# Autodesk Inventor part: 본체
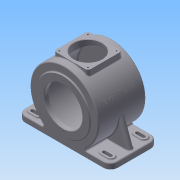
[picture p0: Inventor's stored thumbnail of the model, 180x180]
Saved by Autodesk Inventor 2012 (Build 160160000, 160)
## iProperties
Created: 2015-06
Part Number: 본체
Material: 알루미늄-6061
Document SubType Name: Modeling
Designer: User
Density: 2.71 g/cm^3
Mass: 3275.37 g
Surface Area: 2299.65 cm^2
Volume: 1208.62 cm^3
Author: User
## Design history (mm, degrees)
sketch "스케치1"
  geometry: C1 r 85 at (0, 0); 1 further point
  constraints: 1 centre point, 1 coincident
  dimensions: "d0" = 170 diameter of C1
extrude "돌출1" new body sketch "스케치1" stored distance "d1" = 118; taper "d2" = 0 deg
node "작업 평면1"
sketch "스케치2"
  geometry: L1 (-97, 59)-(97, 59); L2 (115, 41)-(115, -41); L3 (97, -59)-(-97, -59); L4 (-115, -41)-(-115, 41); A1 r 18 centre (-97, 41) between (-97, 59) and (-115, 41); A2 r 18 centre (-97, -41) between (-115, -41) and (-97, -59); A3 r 18 centre (97, -41) between (97, -59) and (115, -41); A4 r 18 centre (97, 41) between (115, 41) and (97, 59); 6 further points
  constraints: 8 end point, 8 point on circle, 8 tangent, 6 point on line, 4 centre point, 3 equal radius, 2 midpoint, 2 parallel, 1 horizontal, 1 horizontal alignment, 1 perpendicular, 1 vertical alignment
  dimensions: "d4" = 118 distance of point (-115, -59) point (-115, 59); "d5" = 230 distance of point (-115, 59) point (115, 59); "d6" = 18 radius of A1
extrude "돌출2" join sketch "스케치2" distance "d7" = 14; taper "d8" = 0 deg
sketch "스케치3"
  geometry: L1 (-42.5, 42.5)-(42.5, 42.5); L2 (42.5, 42.5)-(42.5, -42.5); L3 (42.5, -42.5)-(-42.5, -42.5); L4 (-42.5, -42.5)-(-42.5, 42.5); 3 further points
  constraints: 8 end point, 2 midpoint, 2 parallel, 2 perpendicular, 1 horizontal, 1 horizontal alignment, 1 vertical alignment
  dimensions: "d9" = 85 distance of L1.start L1.end
extrude "돌출3" join sketch "스케치3" distance "d10" = 88; taper "d11" = 0 deg
sketch "스케치4"
  geometry: C1 r 65 at (0, 0); A1 r 85 centre (0, 0) between (46.733, -71) and (-46.733, -71) reference
  constraints: 1 centre point, 1 coincident
  dimensions: "d12" = 130 diameter of C1
extrude "돌출4" join sketch "스케치4" distance "d13" = 3; taper "d14" = 0 deg
sketch "스케치5"
  geometry: C1 r 65 at (0, 0); A1 r 85 centre (0, 0) between (46.733, -71) and (-46.733, -71) reference
  constraints: 1 centre point, 1 coincident
  dimensions: "d15" = 130 diameter of C1
extrude "돌출5" join sketch "스케치5" distance "d16" = 13; taper "d17" = 0 deg
sketch "스케치6"
  geometry: L1 (-46.733, -59)-(-97, -59) reference; L2 (-97, 50)-(-81, 50); L3 (-81, 32)-(-97, 32); L4 (-97, -32)-(-81, -32); L5 (-81, -50)-(-97, -50); L6 (81, 50)-(97, 50); L7 (97, 32)-(81, 32); L8 (81, -32)-(97, -32); L9 (97, -50)-(81, -50); L10 (115, -41)-(115, 41) reference; L11 (-81, 45)-(-97, 45); L12 (-97, 37)-(-81, 37); L13 (97, 45)-(81, 45); L14 (81, 37)-(97, 37); L15 (97, -37)-(81, -37); L16 (81, -45)-(97, -45); L17 (-81, -37)-(-97, -37); L18 (-97, -45)-(-81, -45); A1 r 18 centre (-97, 41) between (-97, 59) and (-115, 41) reference; A2 r 18 centre (-97, -41) between (-115, -41) and (-97, -59) reference; A3 r 9 centre (-81, 41) between (-81, 32) and (-81, 50); A4 r 9 centre (-97, 41) between (-97, 50) and (-97, 32); A5 r 9 centre (-81, -41) between (-81, -50) and (-81, -32); A6 r 9 centre (-97, -41) between (-97, -32) and (-97, -50); A7 r 9 centre (97, 41) between (97, 32) and (97, 50); A8 r 9 centre (81, 41) between (81, 50) and (81, 32); A9 r 9 centre (97, -41) between (97, -50) and (97, -32); A10 r 9 centre (81, -41) between (81, -32) and (81, -50); A11 r 4 centre (-97, 41) between (-97, 45) and (-97, 37); A12 r 4 centre (-81, 41) between (-81, 37) and (-81, 45); A13 r 4 centre (81, 41) between (81, 45) and (81, 37); A14 r 4 centre (97, 41) between (97, 37) and (97, 45); A15 r 4 centre (81, -41) between (81, -37) and (81, -45); A16 r 4 centre (97, -41) between (97, -45) and (97, -37); A17 r 4 centre (-97, -41) between (-97, -37) and (-97, -45); A18 r 4 centre (-81, -41) between (-81, -45) and (-81, -37); 1 further point
  constraints: 32 end point, 32 point on circle, 16 centre point, 16 tangent, 12 parallel, 6 equal radius, 4 coincident, 2 equal length, 2 horizontal alignment, 2 vertical alignment, 12 other
  dimensions: "d18" = 16 distance of A3.centre A1.centre; "d19" = 18 distance between parallel lines of L3 L2; "d20" = 18 distance from line of A7.centre L10; "d21" = 8 distance between parallel lines of L12 L11
extrude "돌출6" join sketch "스케치6" distance "d22" = 3; taper "d23" = 0 deg
extrude "돌출7" cut sketch "스케치6" stored distance "d24" = 30; taper "d25" = 0 deg
sketch "스케치7"
  geometry: L1 (-115, -71)-(-97, -71) reference; L2 (-109, -71)-(-84.87, -4.703); L3 (97, -71)-(115, -71) reference; L4 (109, -71)-(84.87, -4.703); L5 (-84.87, -4.703)-(84.87, -4.703); L6 (-109, -71)-(109, -71); A1 r 85 centre (0, 0) between (46.733, -71) and (-46.733, -71) reference; 1 further point
  constraints: 8 end point, 2 point on circle, 2 point on line
  dimensions: "d26" = 6 distance of L2.start L1.start; "d27" = 110 deg angle of L2 L1; "d28" = 6 distance of L3.end L4.start; "d29" = 110 deg angle of L3 L4
extrude "돌출8" join sketch "스케치7" stored distance "d30" = 15; taper "d31" = 0 deg
node "작업 평면2"
  node "작업축2"
sketch "스케치11"
  geometry: L1 (40.533, -6.549)-(-40.533, -6.549); L2 (-40.533, -6.549)-(-40.533, 6.549); L3 (-40.533, 6.549)-(40.533, 6.549); L4 (40.533, 6.549)-(40.533, -6.549); 4 further points
  constraints: 2 horizontal alignment, 2 midpoint, 1 coincident, 1 vertical alignment, 2 other
feature "엠보싱1" sketch "스케치11" dims "d0" = 170, "d61" = 0.5, "d62" = 0
sketch "스케치8"
  geometry: L1 (-85, 82.6)-(-85, -82.6) reference; L2 (88, 42.5)-(88, -42.5) reference; L3 (-65, 59)-(65, 59) reference; L4 (65, -59)-(-65, -59) reference; L5 (0, 51)-(77, 51); L6 (77, 51)-(77, -51); L7 (77, -51)-(0, -51); L8 (0, 51)-(0, -51); 1 further point
  constraints: 10 end point, 3 parallel, 1 vertical, 1 vertical alignment
  dimensions: "d32" = 8 distance between parallel lines of L4 L7; "d33" = 8 distance between parallel lines of L5 L3; "d34" = 11 distance between parallel lines of L2 L6
revolve "회전1" sketch "스케치8" stored, may be unused: angle "d35" = 90 deg
hole "구멍1" diameter "d38" = 95; stored, may be unused: countersink angle "d42" = 90 deg, drill point angle "d44" = 118 deg; dims "d36" = 10, "d37" = 10, "d39" = 6, "d40" = 4, "d41" = 2, "d43" = 50
sketch "스케치9"
  geometry: C1 r 35 at (0, 0); 1 further point
  constraints: 1 centre point, 1 coincident
  dimensions: "d45" = 70 diameter of C1
extrude "돌출9" cut sketch "스케치9" distance "d46" = 30; taper "d47" = 0 deg
sketch "스케치10"
  geometry: C1 r 77 at (0, 0) reference; C2 r 31 at (0, 0)
  constraints: 1 centre point, 1 coincident
  dimensions: "d48" = 62 diameter of C2
extrude "돌출10" join sketch "스케치10" distance "d49" = 3.5; taper "d50" = -25 deg
hole "구멍2" diameter "d53" = 30; stored, may be unused: countersink angle "d57" = 90 deg, drill point angle "d59" = 0 deg; dims "d51" = 10, "d52" = 10, "d54" = 6, "d55" = 47, "d56" = 14, "d58" = 17
sketch "스케치12"
  geometry: L1 (-35.5, 35.5)-(35.5, 35.5); L2 (35.5, 35.5)-(35.5, -35.5); L3 (35.5, -35.5)-(-35.5, -35.5); L4 (-35.5, -35.5)-(-35.5, 35.5); C1 r 35 at (0, 0) reference; 6 further points
  constraints: 8 end point, 4 coincident, 2 midpoint, 2 parallel, 2 perpendicular, 1 horizontal, 1 horizontal alignment, 1 vertical alignment
  dimensions: "d63" = 71 distance of L1.start L1.end
hole "구멍3" sketch "스케치12" at (-35.5, 35.5), (35.5, 35.5), (35.5, -35.5), (-35.5, -35.5) diameter "d64" = 3.242; stored, may be unused: countersink angle "d68" = 90 deg, drill point angle "d70" = 0 deg; dims "d65" = 10, "d66" = 47, "d67" = 14, "d69" = 13
chamfer "모따기1" distance "d71" = 1; stored, may be unused: second distance "d72" = 2, angle "d73" = 45 deg
chamfer "모따기2" distance "d74" = 1; stored, may be unused: second distance "d75" = 2, angle "d76" = 45 deg
chamfer "모따기3" distance "d77" = 1; stored, may be unused: second distance "d78" = 2, angle "d79" = 45 deg
fillet "모깎기1" dims "d80" = 7
fillet "모깎기2" dims "d81" = 3
fillet "모깎기3" dims "d82" = 3
fillet "모깎기4" dims "d83" = 3
fillet "모깎기5" dims "d84" = 3
fillet "모깎기6" dims "d85" = 7.5
sketch "스케치13"
  geometry: C1 r 65 at (0, 0) reference; 1 further point
  constraints: 1 vertical alignment
  dimensions: "d86" = 55 distance of point (0, 55) C1.centre
hole "구멍4" sketch "스케치13" at (0, 55) diameter "d87" = 3.242; stored, may be unused: countersink angle "d91" = 90 deg, drill point angle "d93" = 118 deg; dims "d88" = 30, "d89" = 4, "d90" = 2, "d92" = 50
fillet "모깎기7" dims "d97" = 0.3
fillet "모깎기8" dims "d98" = 7.5
fillet "모깎기9" dims "d99" = 3
fillet "모깎기10" dims "d100" = 3
fillet "모깎기11" dims "d101" = 3
fillet "모깎기12" dims "d102" = 3
fillet "모깎기13" dims "d103" = 3
node "솔리드1"
pattern_circular "원형 패턴1" dims angle "d95" = 360 deg
other parameters: "d3" = -85, "d60" = -65 deg
